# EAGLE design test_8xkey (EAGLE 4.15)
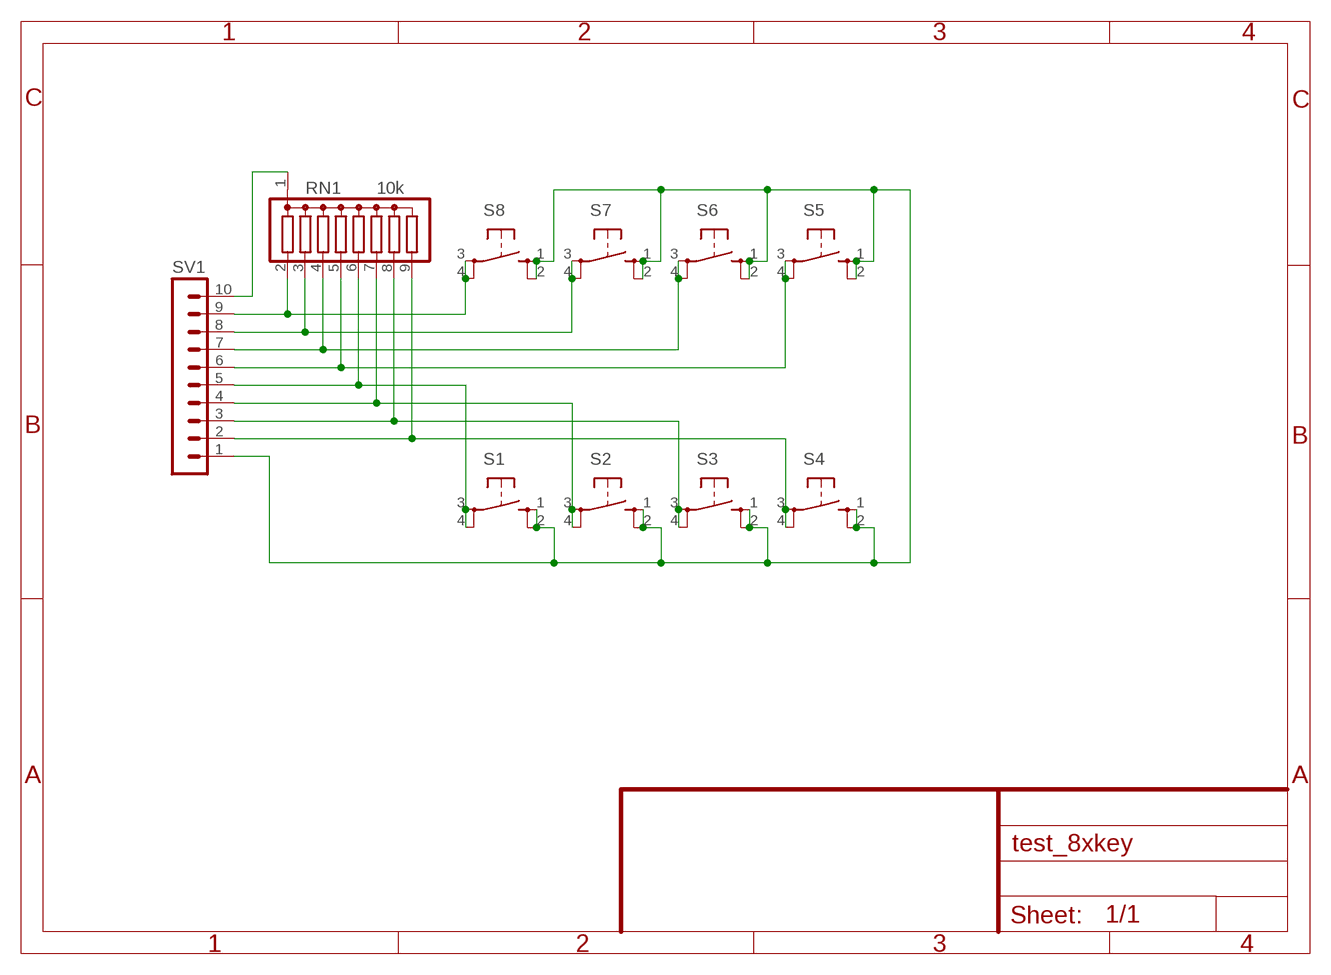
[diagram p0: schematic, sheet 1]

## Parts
RN1  10k  G08R  [SIL9]
S1  10XX-RASTER  [B3F-10XX_RASTER]
S2  10XX-RASTER  [B3F-10XX_RASTER]
S3  10XX-RASTER  [B3F-10XX_RASTER]
S4  10XX-RASTER  [B3F-10XX_RASTER]
S5  10XX-RASTER  [B3F-10XX_RASTER]
S6  10XX-RASTER  [B3F-10XX_RASTER]
S7  10XX-RASTER  [B3F-10XX_RASTER]
S8  10XX-RASTER  [B3F-10XX_RASTER]
SV1  MA10-1W  [MA10-1W]

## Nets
N$1: RN1.2 S8.3 S8.4 SV1.9
N$2: RN1.3 S7.3 S7.4 SV1.8
N$3: RN1.4 S6.3 S6.4 SV1.7
N$4: RN1.5 S5.3 S5.4 SV1.6
N$5: RN1.6 S1.3 S1.4 SV1.5
N$6: RN1.7 S2.3 S2.4 SV1.4
N$7: RN1.8 S3.3 S3.4 SV1.3
N$8: RN1.9 S4.3 S4.4 SV1.2
N$9: RN1.1 SV1.10
VSS: S1.1 S1.2 S2.1 S2.2 S3.1 S3.2 S4.1 S4.2 S5.1 S5.2 S6.1 S6.2 S7.1 S7.2 S8.1 S8.2 SV1.1

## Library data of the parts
RN1 = resistor-sil:G08R: SIL RESISTOR
S1-S8 = KEY_B:10XX-RASTER
SV1 = con-lstb:MA10-1W: PIN HEADER

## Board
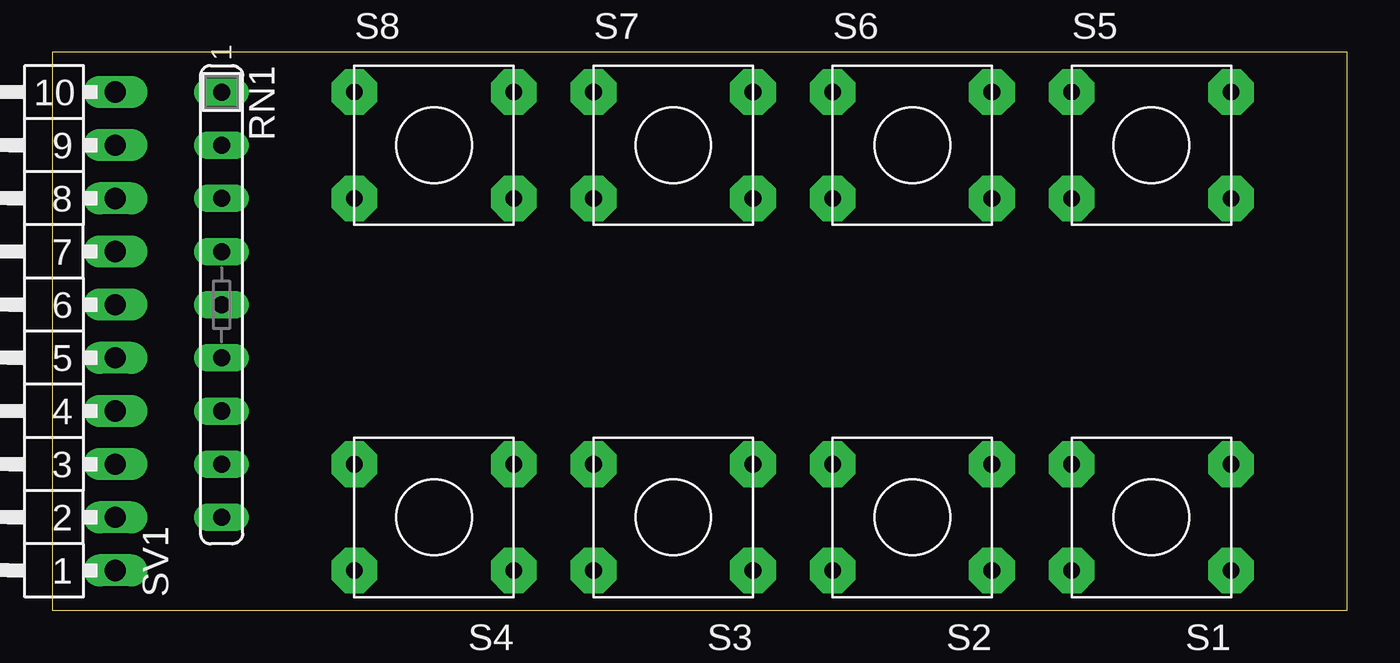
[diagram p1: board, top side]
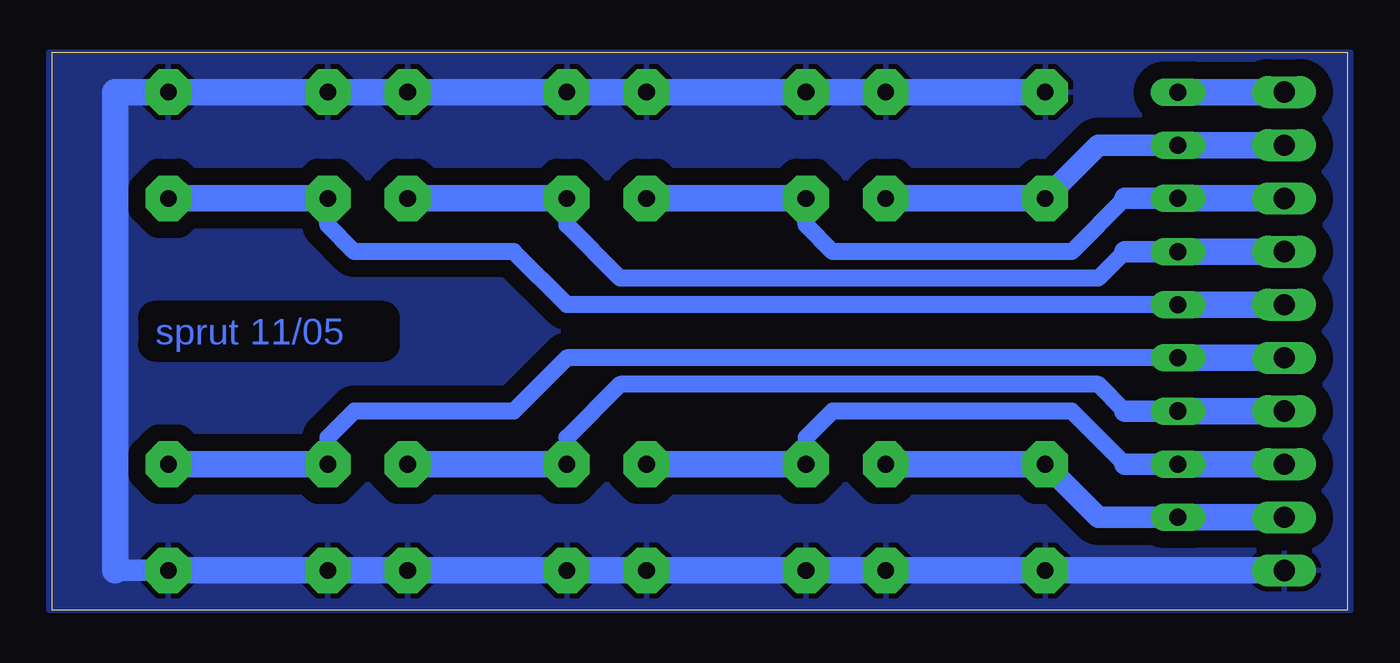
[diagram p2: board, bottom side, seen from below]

Size 61.9 x 26.66 mm. Coordinates in mm from the lower left corner, seen from the top.
Outline: 0,0 61.9,0 61.9,26.66 0,26.66 0,0
Copper layers (1*16): Top 0.035mm / dielectric 1.5mm / Bottom 0.035mm
Design rules "default": minimum track width 10mil, minimum drill 10mil, track to track 8mil, track to pad 8mil, pad to pad 8mil, via to via 8mil, smd to smd 8mil, copper to edge 0mil, drill to drill 8mil, minimum pad ring 10mil, minimum via ring 8mil, stop-mask expansion 4mil, vias tented up to drill 0mil, thermal gap 10mil

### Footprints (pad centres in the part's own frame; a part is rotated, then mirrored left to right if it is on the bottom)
SIL9 = drill 0.813 long: 1 -10.16,0; 2 -7.62,0; 3 -5.08,0; 4 -2.54,0; 5 0,0; 6 2.54,0; 7 5.08,0; 8 7.62,0; 9 10.16,0
B3F-10XX_RASTER = drill 0.8 pad 2.184 octagon: 1 -3.81,2.54; 2 3.81,2.54; 3 -3.81,-2.54; 4 3.81,-2.54
MA10-1W = drill 1.016 long: 1 -11.43,0; 2 -8.89,0; 3 -6.35,0; 4 -3.81,0; 5 -1.27,0; 6 1.27,0; 7 3.81,0; 8 6.35,0; 9 8.89,0; 10 11.43,0

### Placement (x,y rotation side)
RN1  8.09,14.6 270 top
S1  52.54,4.44 180 top
S2  41.11,4.44 180 top
S3  29.68,4.44 180 top
S4  18.25,4.44 180 top
S5  52.54,22.22 0 top
S6  41.11,22.22 0 top
S7  29.68,22.22 0 top
S8  18.25,22.22 0 top
SV1  3.01,13.33 90 top

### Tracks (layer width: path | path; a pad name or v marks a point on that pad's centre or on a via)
N$1
  Bottom 1.016: RN1.2 11.9,22.22 S8.3
  Bottom 1.27: SV1.9 RN1.2 | S8.3 S8.4
N$2
  Bottom 0.813: 10.63,19.68 13.17,17.14 24.6,17.14 25.87,18.41 S7.3
  Bottom 1.016: RN1.3 10.63,19.68
  Bottom 1.27: SV1.8 RN1.3 | S7.3 S7.4
N$3
  Bottom 0.813: 10.63,17.14 11.9,15.87 34.76,15.87 37.3,18.41 S6.3
  Bottom 1.016: RN1.4 10.63,17.14
  Bottom 1.27: SV1.7 RN1.4 | S6.3 S6.4
N$4
  Bottom 0.813: RN1.5 37.3,14.6 39.84,17.14 47.46,17.14 48.73,18.41 S5.3
  Bottom 1.27: SV1.6 RN1.5 | S5.3 S5.4
N$5
  Bottom 0.813: RN1.6 37.3,12.06 39.84,9.52 47.46,9.52 48.73,8.25 S1.4
  Bottom 1.27: SV1.5 RN1.6 | S1.4 S1.3
N$6
  Bottom 0.813: 10.63,9.52 11.9,10.79 34.76,10.79 37.3,8.25 S2.4
  Bottom 1.016: RN1.7 10.63,9.52
  Bottom 1.27: SV1.4 RN1.7 | S2.4 S2.3
N$7
  Bottom 0.813: 10.63,6.98 13.17,9.52 24.6,9.52 25.87,8.25 S3.4
  Bottom 1.016: RN1.8 10.63,6.98
  Bottom 1.27: SV1.3 RN1.8 | S3.4 S3.3
N$8
  Bottom 1.016: RN1.9 11.9,4.44 S4.4
  Bottom 1.27: SV1.2 RN1.9 | S4.4 S4.3
N$9
  Bottom 1.27: SV1.10 RN1.1
VSS
  Bottom 0.406: S5.1 S5.2
  Bottom 1.016: S1.1 58.89,1.9
  Bottom 1.27: SV1.1 S4.2 S4.1 S3.2 S3.1 S2.2 S2.1 S1.2 S1.1 | S8.1 S8.2 S7.1 S7.2 S6.1 S6.2 S5.1 58.89,24.76 58.89,1.9
  pour Bottom (isolate 0.813): -0.17,0 -0.17,26.67 62.06,26.67 62.06,0

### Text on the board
Bottom: sprut 11/05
